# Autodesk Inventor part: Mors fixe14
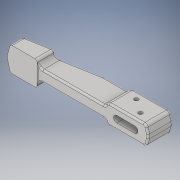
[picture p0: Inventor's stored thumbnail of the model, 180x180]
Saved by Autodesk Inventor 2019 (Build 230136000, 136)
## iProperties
Created: 2002-03
Part Number: Mors fixe14
Material: Générique
Document SubType Name: Modeling
Designer: si-nd67
Density: 1 g/cm^3
Appearance: Par défaut
Author: si-nd67
Sending System: SolidWorks 2014
Last Author: tjost
Last Saved: 2019-02-07
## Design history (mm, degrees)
feature "Enlèv. mat.-Extru.4"
node "Solide1"
